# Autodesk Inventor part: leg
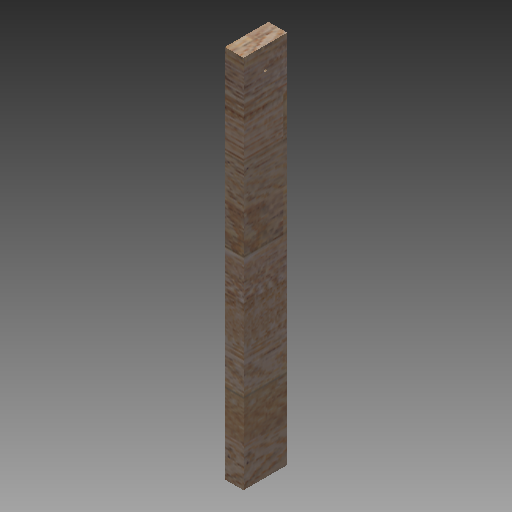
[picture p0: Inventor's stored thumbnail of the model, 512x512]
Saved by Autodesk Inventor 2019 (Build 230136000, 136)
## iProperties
Created: 2013-07
Part Number: leg
Material: Generic
Document SubType Name: Modeling
Designer: Patrick Rice
Density: 1 g/cm^3
Appearance: Red Oak - Natural
Author: Patrick Rice
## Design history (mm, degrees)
sketch "Sketch1"
  geometry: L1 (0, 0)-(-38.1, 0); L2 (-38.1, 0)-(-38.1, 88.9); L3 (-38.1, 88.9)-(0, 88.9); L4 (0, 88.9)-(0, 0); L5 (0, 38.1)-(0, 0)
  constraints: 10 end point, 2 parallel, 1 horizontal, 1 perpendicular
  dimensions: "d0" = 38.1 distance of L2.end L3.end; "d1" = 88.9 distance of L1.end L2.end
extrude "Extrusion1" new body sketch "Sketch1" distance "d4" = 762; taper "d5" = 0 deg
hole "Hole1" diameter "d8" = 6.35; stored, may be unused: countersink angle "d12" = 82 deg, drill point angle "d14" = 118 deg; dims "d6" = 44.323, "d7" = 44.45, "d9" = 19.05, "d10" = 19.05, "d11" = 12.7, "d13" = 25.4
body "Solid1"
